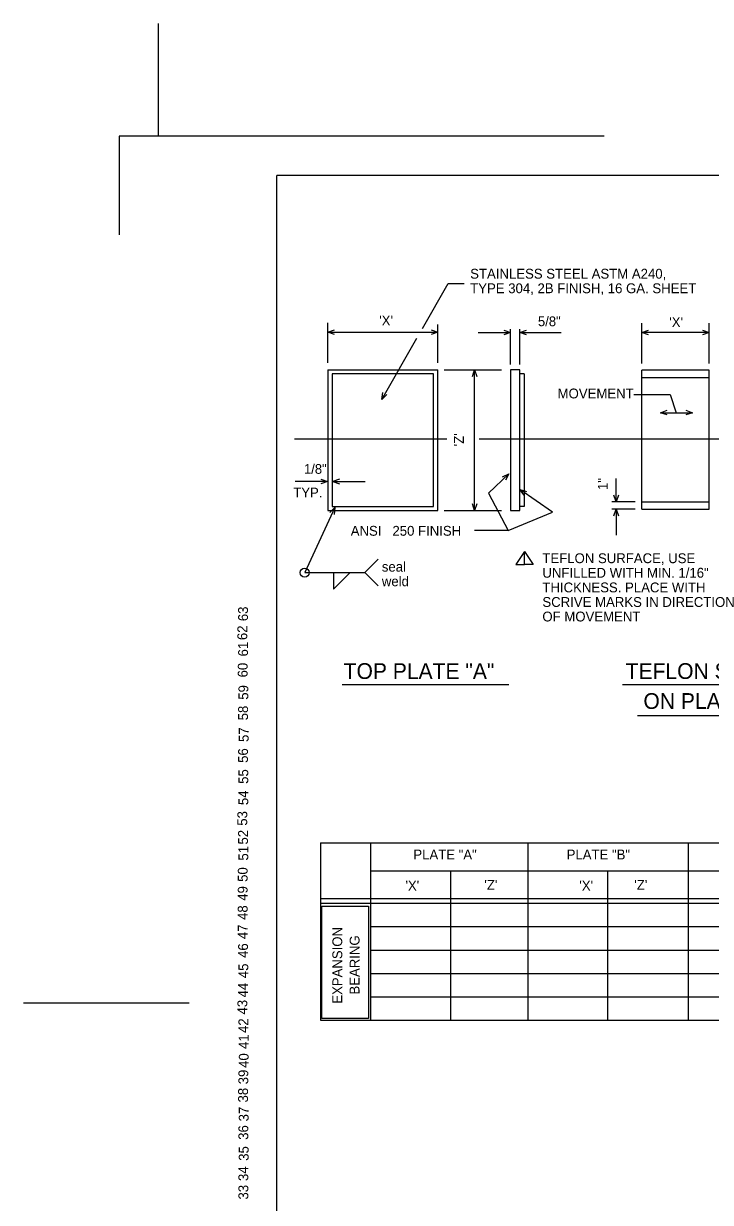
# Model space of a CAD drawing. Extents: x -1.11 to 1.92, y -1.37 to 1.11.
# Drawn here: x -1.114 to -0.387, y -0.135 to 1.113 of the extents above; entities that cross this region are included whole.
import ezdxf

# ---------------------------------------------------------------- set-up
doc = ezdxf.new("R2010")
doc.units = 0
for name, color, linetype in [('Level 1', 7, 'Continuous'), ('Level 2', 7, 'Continuous'), ('Level 33', 7, 'Continuous'), ('Level 34', 7, 'Continuous'), ('Level 35', 7, 'Continuous'), ('Level 36', 7, 'Continuous'), ('Level 37', 7, 'Continuous'), ('Level 38', 7, 'Continuous'), ('Level 39', 7, 'Continuous'), ('Level 40', 7, 'Continuous'), ('Level 41', 7, 'Continuous'), ('Level 42', 7, 'Continuous'), ('Level 43', 7, 'Continuous'), ('Level 44', 7, 'Continuous'), ('Level 45', 7, 'Continuous'), ('Level 46', 7, 'Continuous'), ('Level 47', 7, 'Continuous'), ('Level 48', 7, 'Continuous'), ('Level 49', 7, 'Continuous'), ('Level 50', 7, 'Continuous'), ('Level 51', 7, 'Continuous'), ('Level 52', 7, 'Continuous'), ('Level 53', 7, 'Continuous'), ('Level 54', 7, 'Continuous'), ('Level 55', 7, 'Continuous'), ('Level 56', 7, 'Continuous'), ('Level 57', 7, 'Continuous'), ('Level 58', 7, 'Continuous'), ('Level 59', 7, 'Continuous'), ('Level 60', 7, 'Continuous'), ('Level 61', 7, 'Continuous'), ('Level 62', 7, 'Continuous'), ('Level 63', 7, 'Continuous')]:
    doc.layers.add(name, color=color, linetype=linetype)

msp = doc.modelspace()

# ---------------------------------------------------------------- linework, layer by layer
at = {"layer": 'Level 1'}
for p, q in [((-0.4998, 0.9937), (-1.0128, 0.9937)), ((-1.0128, 0.9937), (-1.0128, 0.8892)), ((-0.846, -0.7994), (-0.846, 0.952)), ((1.7708, 0.952), (-0.846, 0.952))]:
    msp.add_line(p, q, dxfattribs=at)
at = {"layer": 'Level 2'}
for p, q in [((-0.9711, 0.9937), (-0.9711, 1.1127)), ((-0.6919, 0.7901), (-0.6646, 0.8377)), ((-0.6646, 0.8377), (-0.6477, 0.8377)), ((-0.7919, 0.7536), (-0.7919, 0.7961)), ((-0.7919, 0.7863), (-0.6758, 0.7863)), ((-0.6758, 0.7536), (-0.6758, 0.7943)), ((-0.6328, 0.7859), (-0.5988, 0.7859)), ((-0.5988, 0.7518), (-0.5988, 0.7894)), ((-0.589, 0.7518), (-0.589, 0.7894)), ((-0.589, 0.7859), (-0.5452, 0.7859)), ((-0.4597, 0.7532), (-0.4597, 0.7957)), ((-0.3885, 0.7859), (-0.4597, 0.7859)), ((-0.3885, 0.7532), (-0.3885, 0.7957)), ((-0.735, 0.715), (-0.6978, 0.7798)), ((-0.7919, 0.7465), (-0.7919, 0.5974)), ((-0.7919, 0.7465), (-0.6758, 0.7465)), ((-0.6802, 0.7421), (-0.7875, 0.7421)), ((-0.7875, 0.7421), (-0.7875, 0.6018)), ((-0.6802, 0.6018), (-0.6802, 0.7421)), ((-0.6758, 0.5974), (-0.6758, 0.7465)), ((-0.6688, 0.7465), (-0.6084, 0.7465)), ((-0.6367, 0.5974), (-0.6367, 0.7465)), ((-0.589, 0.7465), (-0.5988, 0.7465)), ((-0.5988, 0.7465), (-0.5988, 0.5974)), ((-0.589, 0.5974), (-0.589, 0.7465)), ((-0.5843, 0.7421), (-0.589, 0.7421)), ((-0.5843, 0.7421), (-0.5843, 0.6018)), ((-0.3885, 0.7461), (-0.4597, 0.7461)), ((-0.4597, 0.5989), (-0.4597, 0.7461)), ((-0.4597, 0.7382), (-0.3885, 0.7382)), ((-0.3885, 0.5989), (-0.3885, 0.7461)), ((-0.4681, 0.7204), (-0.4297, 0.7204)), ((-0.4297, 0.7204), (-0.4233, 0.701)), ((-0.4402, 0.701), (-0.4063, 0.701)), ((-0.8272, 0.6733), (-0.666, 0.6733)), ((-0.632, 0.6733), (-0.3766, 0.6733)), ((-0.6005, 0.6363), (-0.6221, 0.6159)), ((-0.7925, 0.6283), (-0.8266, 0.6283)), ((-0.7996, 0.6307), (-0.7925, 0.6283)), ((-0.7925, 0.6283), (-0.7996, 0.6258)), ((-0.7796, 0.6307), (-0.7867, 0.6283)), ((-0.7867, 0.6283), (-0.7526, 0.6283)), ((-0.7867, 0.6283), (-0.7796, 0.6258)), ((-0.487, 0.6068), (-0.487, 0.6315)), ((-0.6221, 0.6159), (-0.6013, 0.5763)), ((-0.5544, 0.5957), (-0.5888, 0.6197)), ((-0.7847, 0.6008), (-0.8165, 0.5318)), ((-0.7875, 0.6018), (-0.6802, 0.6018)), ((-0.5843, 0.6018), (-0.589, 0.6018)), ((-0.4667, 0.6068), (-0.4915, 0.6068)), ((-0.4667, 0.5989), (-0.4915, 0.5989)), ((-0.487, 0.5989), (-0.487, 0.5715)), ((-0.4597, 0.6068), (-0.3885, 0.6068)), ((-0.4597, 0.5989), (-0.3885, 0.5989)), ((-0.7919, 0.5974), (-0.6758, 0.5974)), ((-0.6688, 0.5974), (-0.6084, 0.5974)), ((-0.6013, 0.5763), (-0.5544, 0.5957)), ((-0.5988, 0.5974), (-0.589, 0.5974)), ((-0.6013, 0.5763), (-0.6369, 0.5763)), ((-0.7528, 0.5318), (-0.7387, 0.5459)), ((-0.8165, 0.5318), (-0.7528, 0.5318)), ((-0.7859, 0.5316), (-0.7859, 0.5144)), ((-0.7859, 0.5144), (-0.769, 0.5313)), ((-0.7528, 0.5318), (-0.7388, 0.5178)), ((-0.777, 0.4134), (-0.6005, 0.4134)), ((-0.4802, 0.4134), (-0.2806, 0.4134)), ((-0.4644, 0.3805), (-0.2958, 0.3805)), ((-0.7998, 0.246), (0.496, 0.246)), ((-0.7998, 0.246), (-0.7998, 0.0583)), ((-0.7468, 0.246), (-0.7468, 0.0583)), ((-0.5803, 0.246), (-0.5803, 0.0583)), ((-0.4108, 0.246), (-0.4108, 0.0583)), ((-0.7468, 0.2164), (0.0903, 0.2164)), ((-0.6621, 0.2164), (-0.6621, 0.0583)), ((-0.4961, 0.2164), (-0.4961, 0.0583)), ((-0.7998, 0.1869), (0.496, 0.1869)), ((-0.7998, 0.182), (-0.7468, 0.182)), ((-0.7521, 0.1869), (-0.7468, 0.1869)), ((-0.7468, 0.182), (0.496, 0.182)), ((-0.7468, 0.1573), (0.4953, 0.1573)), ((-0.7468, 0.1325), (0.496, 0.1325)), ((-0.7468, 0.1078), (0.4953, 0.1078)), ((-0.7468, 0.083), (0.496, 0.083)), ((-0.7998, 0.0583), (0.4953, 0.0583))]:
    msp.add_line(p, q, dxfattribs=at)
for points in [[(-0.7848, 0.7838), (-0.7919, 0.7863), (-0.7848, 0.7887)], [(-0.6828, 0.7887), (-0.6758, 0.7863), (-0.6828, 0.7838)], [(-0.6058, 0.7883), (-0.5988, 0.7859), (-0.6058, 0.7835)], [(-0.5819, 0.7835), (-0.589, 0.7859), (-0.5819, 0.7883)], [(-0.4526, 0.7835), (-0.4597, 0.7859), (-0.4526, 0.7883)], [(-0.3956, 0.7883), (-0.3885, 0.7859), (-0.3956, 0.7835)], [(-0.6391, 0.7394), (-0.6367, 0.7465), (-0.6343, 0.7394)], [(-0.7295, 0.7201), (-0.735, 0.715), (-0.7338, 0.7224)], [(-0.4331, 0.6986), (-0.4402, 0.701), (-0.4331, 0.7035)], [(-0.4134, 0.7035), (-0.4063, 0.701), (-0.4134, 0.6986)], [(-0.6073, 0.6332), (-0.6005, 0.6363), (-0.6039, 0.6297)], [(-0.5844, 0.6137), (-0.5888, 0.6197), (-0.5817, 0.6177)], [(-0.4846, 0.6139), (-0.487, 0.6068), (-0.4895, 0.6139)], [(-0.7898, 0.5954), (-0.7847, 0.6008), (-0.7854, 0.5934)], [(-0.6343, 0.6045), (-0.6367, 0.5974), (-0.6391, 0.6045)], [(-0.4895, 0.5918), (-0.487, 0.5989), (-0.4846, 0.5918)], [(-0.5839, 0.5542), (-0.5931, 0.5402), (-0.5839, 0.5402)], [(-0.5839, 0.5542), (-0.5748, 0.5402), (-0.5839, 0.5402)]]:
    msp.add_lwpolyline(points, dxfattribs=at)
for points in [[(-0.5839, 0.5542), (-0.5748, 0.5402), (-0.5839, 0.5402)], [(-0.7983, 0.1789), (-0.749, 0.1789), (-0.749, 0.0601), (-0.7983, 0.0601)]]:
    msp.add_lwpolyline(points, close=True, dxfattribs=at)
msp.add_circle((-0.8165, 0.5318), 0.00472, dxfattribs=at)
at = {"layer": 'Level 37'}
msp.add_line((-0.9389, 0.0763), (-1.114, 0.0763), dxfattribs=at)

# ---------------------------------------------------------------- texts
at = {"layer": 'Level 2'}
for s, height, p in [('STAINLESS STEEL ASTM A240,', 0.010417, (-0.6414, 0.8428)), ('TYPE 304, 2B FINISH, 16 GA. SHEET', 0.010417, (-0.6414, 0.8274)), ("'X'", 0.01042, (-0.7377, 0.7933)), ('5/8"', 0.01033, (-0.5697, 0.7925)), ("'X'", 0.01042, (-0.4308, 0.7916)), ('MOVEMENT', 0.01042, (-0.5489, 0.7161)), ('1/8"', 0.01033, (-0.8173, 0.6363)), ('TYP.', 0.01033, (-0.8285, 0.6113)), ('ANSI   250 FINISH', 0.010417, (-0.7678, 0.5708)), ('TEFLON SURFACE, USE', 0.010417, (-0.565, 0.5418)), ('seal', 0.01042, (-0.7349, 0.5328)), ('UNFILLED WITH MIN. 1/16"', 0.010417, (-0.565, 0.5264)), ('weld', 0.01042, (-0.7349, 0.5174)), ('THICKNESS. PLACE WITH', 0.010417, (-0.565, 0.5109)), ('SCRIVE MARKS IN DIRECTION', 0.010417, (-0.565, 0.4955)), ('OF MOVEMENT', 0.010417, (-0.565, 0.4801)), ('TOP PLATE "A"', 0.016667, (-0.7753, 0.4193)), ('TEFLON SURFACE', 0.016667, (-0.4769, 0.4193)), ('ON PLATE "B"', 0.016667, (-0.4581, 0.3876)), ('PLATE "A"', 0.0104, (-0.7015, 0.2283)), ('PLATE "B"', 0.0104, (-0.5393, 0.2283)), ("'X'", 0.0104, (-0.7099, 0.1954)), ("'Z'", 0.0104, (-0.6264, 0.1962)), ("'X'", 0.0104, (-0.5259, 0.1954)), ("'Z'", 0.0104, (-0.4678, 0.1962))]:
    msp.add_text(s, height=height, dxfattribs=at).set_placement(p)
for s, height, p in [("'Z'", 0.01042, (-0.6481, 0.6654)), ('1"', 0.01042, (-0.4959, 0.6191)), ('EXPANSION', 0.0104, (-0.7768, 0.0757)), ('BEARING', 0.0104, (-0.7585, 0.0854))]:
    msp.add_text(s, height=height, rotation=90, dxfattribs=at).set_placement(p)
at = {"layer": 'Level 33'}
msp.add_text('33', height=0.01041, rotation=90, dxfattribs=at).set_placement((-0.8762, -0.1315))
at = {"layer": 'Level 34'}
msp.add_text('34', height=0.01041, rotation=90, dxfattribs=at).set_placement((-0.8762, -0.1119))
at = {"layer": 'Level 35'}
msp.add_text('35', height=0.01041, rotation=90, dxfattribs=at).set_placement((-0.8758, -0.0905))
at = {"layer": 'Level 36'}
msp.add_text('36', height=0.01041, rotation=90, dxfattribs=at).set_placement((-0.8762, -0.0683))
at = {"layer": 'Level 37'}
msp.add_text('37', height=0.01041, rotation=90, dxfattribs=at).set_placement((-0.8758, -0.0488))
at = {"layer": 'Level 38'}
msp.add_text('38', height=0.01041, rotation=90, dxfattribs=at).set_placement((-0.8765, -0.0288))
at = {"layer": 'Level 39'}
msp.add_text('39', height=0.01041, rotation=90, dxfattribs=at).set_placement((-0.8762, -0.0096))
at = {"layer": 'Level 40'}
msp.add_text('40', height=0.01041, rotation=90, dxfattribs=at).set_placement((-0.8758, 0.0078))
at = {"layer": 'Level 41'}
msp.add_text('41', height=0.01041, rotation=90, dxfattribs=at).set_placement((-0.8758, 0.0277))
at = {"layer": 'Level 42'}
msp.add_text('42', height=0.01041, rotation=90, dxfattribs=at).set_placement((-0.8762, 0.0447))
at = {"layer": 'Level 43'}
msp.add_text('43', height=0.01041, rotation=90, dxfattribs=at).set_placement((-0.8773, 0.0643))
at = {"layer": 'Level 44'}
msp.add_text('44', height=0.01041, rotation=90, dxfattribs=at).set_placement((-0.8765, 0.0823))
at = {"layer": 'Level 45'}
msp.add_text('45', height=0.01041, rotation=90, dxfattribs=at).set_placement((-0.8762, 0.1027))
at = {"layer": 'Level 46'}
msp.add_text('46', height=0.01041, rotation=90, dxfattribs=at).set_placement((-0.8765, 0.1241))
at = {"layer": 'Level 47'}
msp.add_text('47', height=0.01041, rotation=90, dxfattribs=at).set_placement((-0.8769, 0.144))
at = {"layer": 'Level 48'}
msp.add_text('48', height=0.01041, rotation=90, dxfattribs=at).set_placement((-0.8769, 0.1643))
at = {"layer": 'Level 49'}
msp.add_text('49', height=0.01041, rotation=90, dxfattribs=at).set_placement((-0.8769, 0.1846))
at = {"layer": 'Level 50'}
msp.add_text('50', height=0.01041, rotation=90, dxfattribs=at).set_placement((-0.8769, 0.2046))
at = {"layer": 'Level 51'}
msp.add_text('51', height=0.01041, rotation=90, dxfattribs=at).set_placement((-0.8762, 0.2271))
at = {"layer": 'Level 52'}
msp.add_text('52', height=0.01041, rotation=90, dxfattribs=at).set_placement((-0.8765, 0.2441))
at = {"layer": 'Level 53'}
msp.add_text('53', height=0.01041, rotation=90, dxfattribs=at).set_placement((-0.8773, 0.264))
at = {"layer": 'Level 54'}
msp.add_text('54', height=0.01041, rotation=90, dxfattribs=at).set_placement((-0.8762, 0.2858))
at = {"layer": 'Level 55'}
msp.add_text('55', height=0.01041, rotation=90, dxfattribs=at).set_placement((-0.8762, 0.3083))
at = {"layer": 'Level 56'}
msp.add_text('56', height=0.01041, rotation=90, dxfattribs=at).set_placement((-0.8765, 0.3305))
at = {"layer": 'Level 57'}
msp.add_text('57', height=0.01041, rotation=90, dxfattribs=at).set_placement((-0.8758, 0.3526))
at = {"layer": 'Level 58'}
msp.add_text('58', height=0.01041, rotation=90, dxfattribs=at).set_placement((-0.8765, 0.3755))
at = {"layer": 'Level 59'}
msp.add_text('59', height=0.01041, rotation=90, dxfattribs=at).set_placement((-0.8762, 0.3973))
at = {"layer": 'Level 60'}
msp.add_text('60', height=0.01041, rotation=90, dxfattribs=at).set_placement((-0.8769, 0.4209))
at = {"layer": 'Level 61'}
msp.add_text('61', height=0.01041, rotation=90, dxfattribs=at).set_placement((-0.8765, 0.4431))
at = {"layer": 'Level 62'}
msp.add_text('62', height=0.01041, rotation=90, dxfattribs=at).set_placement((-0.8773, 0.4604))
at = {"layer": 'Level 63'}
msp.add_text('63', height=0.01041, rotation=90, dxfattribs=at).set_placement((-0.8765, 0.4804))

doc.saveas('drawing.dxf')
